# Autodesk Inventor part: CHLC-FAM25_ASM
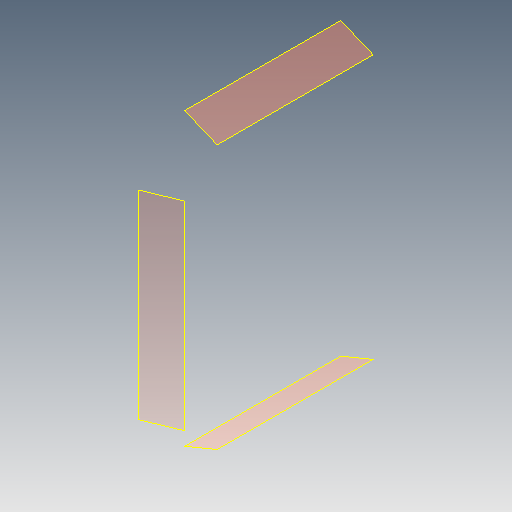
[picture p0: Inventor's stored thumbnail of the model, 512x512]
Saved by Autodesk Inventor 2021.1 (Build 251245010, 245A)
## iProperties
Created: 2021-05
Part Number: CHLC-FAM25_ASM
Material: Ogólny
Document SubType Name: Modeling
Designer: user
Density: 1 g/cm^3
Appearance: Domyślna
Author: user
Revision Number: ÈÎºÎ
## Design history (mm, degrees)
feature "Złożony1"
body "Srf1"
